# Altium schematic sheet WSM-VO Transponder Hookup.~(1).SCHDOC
size B; Organization: Monterey Bay Aquarium Research Institute; Address1: 7700 Sandholdt Rd; Address2: Moss Landing, CA 95039-9644; CompanyName: MBARI
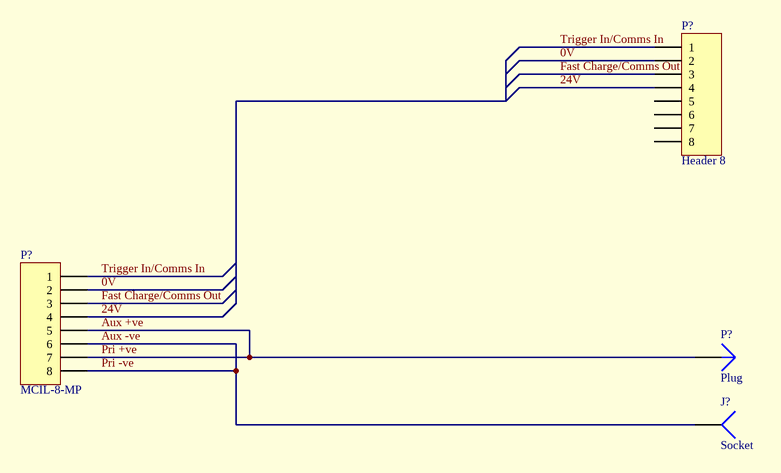
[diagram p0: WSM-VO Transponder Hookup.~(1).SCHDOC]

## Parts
(Parts that share a designator on the sheet are numbered #1, #2 ... from top to bottom, then left to right.)
J?  Socket  [PIN1]
P?#1  Header 8  [HDR1X8]
P?#2  MCIL-8-MP  [HDR1X8]
P?#3  Plug  [PIN1]

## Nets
0V: P?#1.2 P?#2.2
24V: P?#1.4 P?#2.4
Aux +ve: P?#2.5 P?#2.7 P?#3.1  [also labelled Pri +ve]
Aux -ve: J?.1 P?#2.6 P?#2.8  [also labelled Pri -ve]
Fast Charge/Comms Out: P?#1.3 P?#2.3
Trigger In/Comms In: P?#1.1 P?#2.1

Not connected (* = marked no-connect by the designer): P?#1 5 6 7 8

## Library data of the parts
P?#1 P?#2 = Header 8: Header, 8-Pin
